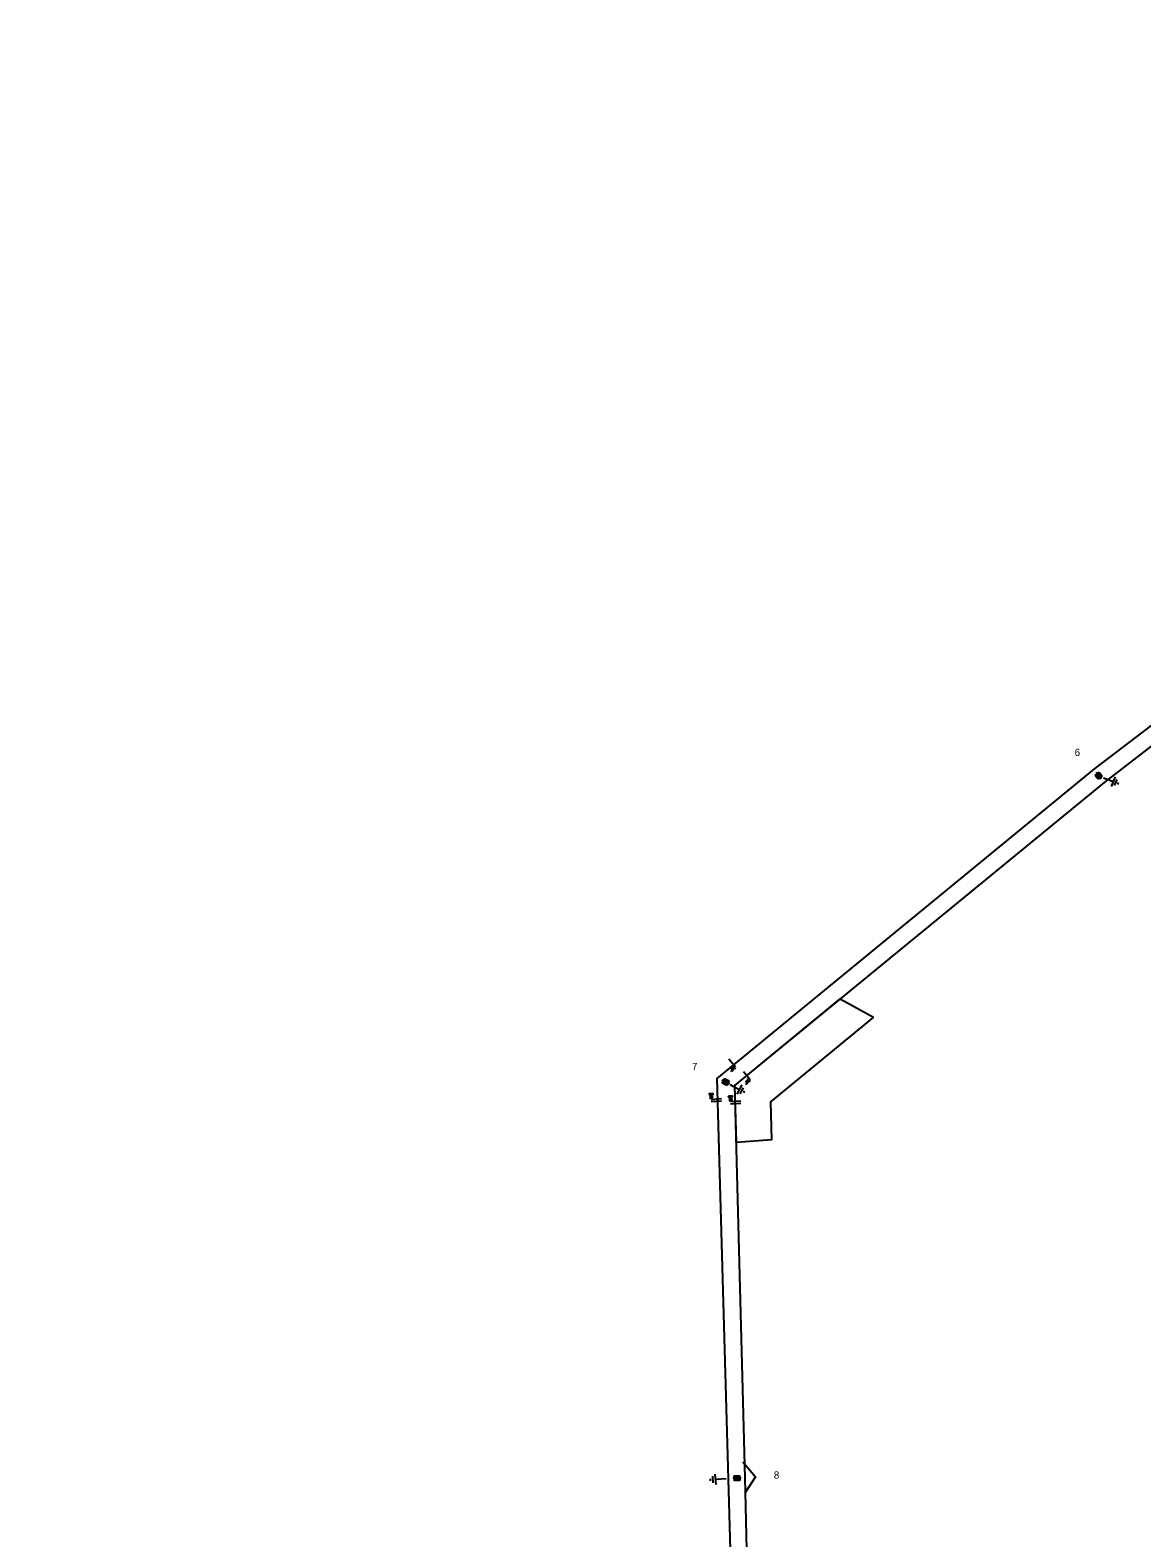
# Model space of a CAD drawing. Extents: x -788491 to -785797, y -1154753 to -1152002.
# Drawn here: x -788109.7 to -787842.2, y -1154362.4 to -1153999.5 of the extents above; entities that cross this region are included whole.
import ezdxf

# ---------------------------------------------------------------- set-up
doc = ezdxf.new("R2010")
doc.units = 0
for name, color, linetype in [('Vrstva 1', 7, 'Continuous'), ('Vrstva 13', 7, 'Continuous'), ('Vrstva 14', 7, 'Continuous'), ('Vrstva 15', 7, 'Continuous'), ('Vrstva 18', 7, 'Continuous'), ('Vrstva 2', 7, 'Continuous'), ('Vrstva 35', 7, 'Continuous')]:
    doc.layers.add(name, color=color, linetype=linetype)

# ---------------------------------------------------------------- blocks, each defined once
blk = doc.blocks.new('VN850')
at = {"layer": 'Vrstva 15'}
for points in [[(-0.56, 1.43), (-0.56, -1.07)], [(-0.01, 1.43), (-0.01, -1.07)], [(-2.09, -0.54), (-1.78, -0.54)], [(-2.09, -1.41), (-2.09, -0.54)], [(-1.78, -1.41), (-2.09, -1.41)], [(-1.78, -0.54), (-1.66, -0.6)], [(-1.67, -1.35), (-1.78, -1.41)], [(-1.59, -1.2), (-1.67, -1.35)], [(-1.66, -0.6), (-1.59, -0.75)], [(-1.59, -0.75), (-1.55, -0.96)], [(-1.55, -0.96), (-1.59, -1.2)], [(-1.26, -0.54), (-1.26, -1.41)], [(-0.85, -0.54), (-1.26, -1.09)], [(-1.13, -0.92), (-0.77, -1.41)]]:
    blk.add_lwpolyline(points, dxfattribs=at)
blk = doc.blocks.new('VN840')
at = {"layer": 'Vrstva 15'}
for points in [[(-0.01, 1.41), (-0.01, -1.09)], [(-1.51, -1.24), (-1.51, -1.15)], [(-1.48, -1.35), (-1.51, -1.24)], [(-1.33, -1.42), (-1.48, -1.35)], [(-1.27, -1.42), (-1.33, -1.42)], [(-1.13, -1.35), (-1.27, -1.42)], [(-1.09, -1.24), (-1.13, -1.35)], [(-1.09, -0.59), (-1.09, -1.24)], [(-0.68, -0.59), (-0.68, -1.42)], [(-0.68, -1.11), (-0.27, -0.59)], [(-0.54, -0.94), (-0.2, -1.42)]]:
    blk.add_lwpolyline(points, dxfattribs=at)
blk = doc.blocks.new('VN860')
at = {"layer": 'Vrstva 15'}
for points in [[(-3.74, 0), (0.01, 2.82)], [(0.01, 2.82), (3.76, 0)]]:
    blk.add_lwpolyline(points, dxfattribs=at)
blk = doc.blocks.new('VN810')
at = {"layer": 'Vrstva 14'}
for points in [[(0, -1.25), (0, -3.75)], [(1.25, -3.75), (-1.25, -3.75)], [(0.77, -4.37), (-0.8, -4.37)], [(0, -5), (-0.25, -5)], [(0.27, -5), (0, -5)]]:
    blk.add_lwpolyline(points, dxfattribs=at)
blk = doc.blocks.new('VN470')
at = {"layer": 'Vrstva 2'}
for points in [[(-1.23, 1.22), (1.23, 1.22)], [(-1.23, -1.23), (-1.23, 1.22)], [(-0.92, 0.9), (0.92, 0.9)], [(-0.92, -0.95), (-0.92, 0.9)], [(-0.61, 0.61), (0.61, 0.61)], [(-0.61, -0.62), (-0.61, 0.61)], [(-0.31, -0.27), (-0.31, 0.34)], [(-0.31, 0.34), (0.31, 0.34)], [(0, 1.22), (0, 1.97)], [(0.31, 0.34), (0.31, -0.27)], [(0.61, 0.61), (0.61, -0.62)], [(0.92, 0.9), (0.92, -0.95)], [(1.23, 1.22), (1.23, -1.23)], [(1.23, -1.23), (-1.23, -1.23)], [(0.92, -0.95), (-0.92, -0.95)], [(0.61, -0.62), (-0.61, -0.62)], [(0.31, -0.27), (-0.31, -0.27)], [(0, -1.23), (0, -1.98)]]:
    blk.add_lwpolyline(points, dxfattribs=at)

msp = doc.modelspace()

# ---------------------------------------------------------------- linework, layer by layer
at = {"layer": 'Vrstva 1'}
for points in [[(-787607.03, -1153915.49), (-787637.43, -1153970.03), (-787646.17, -1153986.09), (-787669.6, -1154026.19), (-787760.49, -1154105.76), (-787790.77, -1154129.38), (-787853.74, -1154177.36), (-787944.45, -1154251.81), (-787941.69, -1154348.3), (-787939.33, -1154432.99), (-788019.18, -1154537.71), (-788103.24, -1154647.83), (-788109.69, -1154656.37)], [(-787851.17, -1154180.56), (-787788.31, -1154132.05), (-787758.04, -1154108.54)], [(-788104.26, -1154657.17), (-788099.34, -1154650.72), (-788016, -1154540.1), (-787935.59, -1154434.83), (-787937.61, -1154347.98), (-787940.11, -1154253.5), (-787851.17, -1154180.56)]]:
    msp.add_lwpolyline(points, dxfattribs=at)
at = {"layer": 'Vrstva 35'}
msp.add_lwpolyline([(-787906.72, -1154237.11), (-787931.5, -1154257.43), (-787931.26, -1154266.56), (-787939.75, -1154267.21), (-787940.11, -1154253.5), (-787914.73, -1154232.69)], close=True, dxfattribs=at)

# ---------------------------------------------------------------- block references
at = {"layer": 'Vrstva 13', "xscale": 0.5}
for p, yscale, rotation in [((-787852.56, -1154178.96), 0.5, 39.069588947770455), ((-787942.32, -1154252.68), 0.5, 63.459766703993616), ((-787939.58, -1154348.01), 0.49999999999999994, -86.20730837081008)]:
    msp.add_blockref('VN470', p, dxfattribs=dict(at, yscale=yscale, rotation=rotation))
at = {"layer": 'Vrstva 15'}
for p, rotation in [((-787852.56, -1154178.96), 67.9066944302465), ((-787942.32, -1154252.68), 61.1481528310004), ((-787940.98, -1154348.09), -86.20730829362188)]:
    msp.add_blockref('VN810', p, dxfattribs=dict(at, rotation=rotation))
at = {"layer": 'Vrstva 18'}
for name, p, rotation in [('VN840', (-787940.62, -1154248.16), 39.069588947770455), ('VN840', (-787937.11, -1154251.24), 39.069980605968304), ('VN850', (-787944.71, -1154257.42), -86.20730830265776), ('VN850', (-787940.06, -1154257.96), -86.2107555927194), ('VN860', (-787937.93, -1154347.85), -86.20730836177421)]:
    msp.add_blockref(name, p, dxfattribs=dict(at, rotation=rotation))

# ---------------------------------------------------------------- texts
at = {"layer": 'Vrstva 14'}
for s, p in [('6', (-787858.33, -1154174.22)), ('7', (-787950.41, -1154249.82)), ('8', (-787930.72, -1154348.14))]:
    msp.add_text(s, height=1.75, dxfattribs=at).set_placement(p)

doc.saveas('drawing.dxf')
